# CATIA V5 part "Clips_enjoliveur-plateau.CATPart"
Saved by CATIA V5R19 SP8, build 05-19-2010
Part number: Clips_enjoliveur-plateau
Nomenclature: 52
Material "Plastique": density 1200 kg/m3, Young's modulus 2.2e+09 Pa, Poisson ratio 0.38, thermal expansion 6.84e-05 1/K
Bounding box of the stored display mesh (mm): x 0 to 7, y -9.997 to 9.997, z -9.997 to 9.997
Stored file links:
  C:\Users\rphgr\Desktop\0_Tapis_TC520B_vitesse\Clips_enjoliveur-plateau.CATPart
  D:\Programmes\DassaultSysteme\win_b64\startup\materials\French\Catalog.CATMaterial
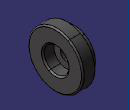
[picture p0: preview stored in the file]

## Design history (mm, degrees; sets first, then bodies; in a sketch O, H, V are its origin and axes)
AxisSystem1: origin (0, 0, 0), X (1, 0, 0), Y (0, 1, 0), Z (0, 0, 1)
Body1 (main body), material "Plastique"
  Sketch1 on ZX plane of AxisSystem1, origin (0, 0, 0), H (0, 0, 1), V (1, 0, 0)
    axis line L1 (0, 58.2518) -> (0, -69.1996)
    point P1 (0, 58.2518)
    point P3 (7.5, 0)
    line L2 (7.5, 0) -> (7.5, 2.7)
    line L3 (7.5, 2.7) -> (10, 2.7)
    line L4 (10, 2.7) -> (10, 7)
    line L5 (10, 7) -> (4.5, 7)
    line L6 (4.5, 7) -> (4.5, 3)
    line L7 (4.5, 3) -> (2.25, 3)
    line L8 (2.25, 3) -> (2.25, 0)
    point P10 (2.25, 0)
    line L9 (2.25, 0) -> (7.5, 0)
    reference intersected line E1 through (0, 0) direction (-1, 0) from YZ plane of AxisSystem1
    reference intersected line E2 through (0, 0) direction (-1, 0) from YZ plane of AxisSystem1
    distance L8 L1 = 2.25
    distance L2 L1 = 7.5
    distance L6 L1 = 4.5
    distance L4 L1 = 10
    distance L3 E1 = 2.7
    distance L7 E2 = 3
    distance L5 L9 = 7
    coincidence: P1 V, P3 H, P10 H
    vertical: L1 V, L2 V, L4 V, L6 V, L8 V
    horizontal: L3 H, L5 H, L7 H, L9 H
  Shaft1: profile Sketch1, axis Sketch1.L1, angle 360
  Fillet1: radius 0.5, on edge [face of Shaft1 from Sketch1.L5 | face of Shaft1 from Sketch1.L4]
  Chamfer1: length 0.5, angle 45, on edge [face of Shaft1 from Sketch1.L6 | face of Shaft1 from Sketch1.L5]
